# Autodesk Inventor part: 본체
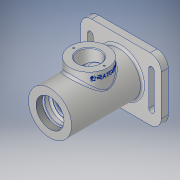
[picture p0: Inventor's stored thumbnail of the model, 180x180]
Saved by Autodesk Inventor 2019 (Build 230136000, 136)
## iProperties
Created: 2021-07
Part Number: 본체
Material: 알루미늄 6061
Document SubType Name: Modeling
Designer: jun-2-10
Mass: 738.051 g
Surface Area: 647.155 cm^2
Volume: 273.352 cm^3
Density: 2.7 g/cm^3
Appearance: 알루미늄 - 평지
Author: jun-2-10
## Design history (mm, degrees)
sketch "스케치1"
  geometry: C1 r 31 at (0, 0); 1 further point
  constraints: 1 centre point, 1 coincident
  dimensions: "d0" = 62 diameter of C1
extrude "돌출1" new body sketch "스케치1" stored distance "d1" = 115; taper "d2" = 0 deg
sketch "스케치2"
  geometry: C1 r 35 at (0, 0); 1 further point
  constraints: 1 centre point, 1 coincident
  dimensions: "d3" = 70 diameter of C1
extrude "돌출2" join sketch "스케치2" distance "d4" = 3; taper "d5" = 0 deg
sketch "스케치3"
  geometry: L1 (-58, 45)-(58, 45); L2 (58, 45)-(58, -45); L3 (58, -45)-(-58, -45); L4 (-58, -45)-(-58, 45); L5 (-58, 45)-(58, -45); L6 (58, 45)-(-58, -45); 1 further point
  constraints: 12 end point, 2 midpoint, 2 parallel, 1 horizontal, 1 perpendicular
  dimensions: "d6" = 116 distance of L1.start L1.end; "d7" = 90 distance of L1.end L2.end
extrude "돌출3" join sketch "스케치3" distance "d8" = 10; taper "d9" = 0 deg
sketch "스케치4"
  geometry: L1 (17.5, 31.5)-(17.5, 20.5); L2 (17.5, 20.5)-(23, 20.5); L3 (26, 17.5)-(26, -14.5); L4 (23, -17.5)-(17.5, -17.5); L5 (17.5, -17.5)-(17.5, -28.5); L6 (17.5, -28.5)-(16, -28.5); L7 (16, -28.5)-(16, -30.5); L8 (13, -33.5)-(10, -33.5); L9 (10, -33.5)-(10, -36.2); L10 (16.779, -45.318)-(22, -57.5); L11 (0, 80.5)-(0, -80.5) reference; L12 (31, -44.5)-(31, 57.5) reference; L13 (-31, -44.5)-(-31, 57.5) reference; L14 (35, -57.5)-(-35, -57.5) reference; L15 (14.022, -43.5)-(12.5, -43.5); L16 (12.5, -43.5)-(12.5, -36.5); L17 (12.2, -36.2)-(10, -36.2); L18 (17.5, 31.5)-(18.5, 31.5); L19 (18.5, 31.5)-(18.5, 33.25); L20 (18.5, 33.25)-(17.5, 33.25); L21 (17.5, 33.25)-(17.5, 36.5); L22 (17.5, 36.5)-(17, 36.5); L23 (20, 39.5)-(20, 45.5); L24 (20, 45.5)-(24, 45.5); L25 (24, 45.5)-(24, 48.5); L26 (24, 48.5)-(21, 48.5); L27 (31, 57.5)-(-31, 57.5) reference; L28 (22, -57.5)-(0, -57.5); L29 (21, 48.5)-(0, 48.5); L30 (0, 48.5)-(0, -57.5); A1 r 3 centre (17, 39.5) between (17, 36.5) and (20, 39.5); A2 r 3 centre (13, -30.5) between (13, -33.5) and (16, -30.5); A3 r 0.3 centre (12.2, -36.5) between (12.5, -36.5) and (12.2, -36.2); A4 r 3 centre (23, 17.5) between (26, 17.5) and (23, 20.5); A5 r 3 centre (23, -14.5) between (23, -17.5) and (26, -14.5); A6 r 3 centre (14.022, -46.5) between (16.779, -45.318) and (14.022, -43.5); 7 further points
  constraints: 50 end point, 20 perpendicular, 12 point on circle, 12 tangent, 10 point on line, 6 centre point, 2 horizontal, 1 equal radius, 1 midpoint
  dimensions: "d11" = 14 vertical distance of L10.end point (16, -43.5); "d12" = 44 diameter of L10.end L11; "d13" = 32 diameter of point (16, -43.5) L11; "d14" = 24 distance between parallel lines of L14 L8; "d15" = 20 diameter of L9 L11; "d16" = 52 diameter of L3 L11; "d17" = 35 diameter of L1 L11; "d18" = 11 distance of L4.end L5.end; "d20" = 7.3 distance of L15.end point (12.5, -36.2); "d21" = 25 diameter of L16 L11; "d22" = 32 diameter of L7 L11; "d23" = 35 diameter of L5 L11; "d24" = 38 distance of point (26, 20.5) point (26, -17.5); "d27" = 12 distance between parallel lines of L27 L24; "d29" = 1.75 distance of L18.end L19.end; "d30" = 37 diameter of L19 L11; "d31" = 35 diameter of L21 L11; "d32" = 21 distance between parallel lines of L27 L22; "d33" = 40 diameter of L23 L11; "d34" = 48 diameter of L25 L11; "d35" = 3 distance of L24.end L25.end; "d37" = 11 distance of L1.start L1.end; "d38" = 3 radius of A1; "d39" = 65 distance from line of L6 L21.end; "d40" = 3 radius of A2 (derived); "d41" = 0.3 radius of A3; "d42" = 3 radius of A4; "d43" = 3 radius of A6 (derived)
revolve "회전1" sketch "스케치4" stored, may be unused: angle "d44" = 90 deg
chamfer "모따기1" distance "d45" = 0.7; stored, may be unused: second distance "d46" = 2, angle "d47" = 30 deg
sketch "스케치7"
  geometry: 2 further points
  constraints: 1 coincident
hole "구멍1" sketch "스케치7" at (0, 0) diameter "d48" = 40.376; stored, may be unused: countersink angle "d52" = 90 deg, drill point angle "d54" = 0 deg; dims "d49" = 9, "d50" = 4, "d51" = 2, "d53" = 9
fillet "모깎기1" dims "d55" = 16
node "작업 평면1"
sketch "스케치9"
  geometry: L1 (0, -80.5)-(0, 80.5) reference; L2 (-81.2, 0)-(81.2, 0) reference; L3 (31, 57.5)-(-31, 57.5) reference; C1 r 27 at (0, 1.5); 1 further point
  constraints: 1 centre point, 1 point on line
  dimensions: "d58" = 54 diameter of C1; "d59" = 56 distance from line of L3 C1.centre
extrude "돌출4" join sketch "스케치9" stored distance "d60" = 10; taper "d61" = 0 deg
sketch "스케치10"
  geometry: C1 r 27 at (0, 0) reference; C2 r 16 at (0, 0); 1 further point
  constraints: 1 centre point, 1 coincident
  dimensions: "d62" = 32 diameter of C2
extrude "돌출5" cut sketch "스케치10" stored distance "d63" = 10; taper "d64" = 0 deg
sketch "스케치11"
  geometry: L1 (0, 82)-(0, -79) reference; L2 (22, 0)-(-22, 0); L3 (-31, -56)-(31, -56) reference; C1 r 16 at (0, 0) reference; C2 r 27 at (0, 0) reference; A1 r 22 centre (0, 0) between (22, 0) and (-22, 0); 3 further points
  constraints: 3 coincident, 2 end point, 2 point on circle, 1 centre point, 1 horizontal
  dimensions: "d65" = 44 diameter of A1; "d66" = 56 distance between parallel lines of L3 L2
hole "구멍2" sketch "스케치11" at (-22, 0), (22, 0) diameter "d67" = 2.459; stored, may be unused: countersink angle "d71" = 90 deg, drill point angle "d73" = 118 deg; dims "d68" = 6, "d69" = 4, "d70" = 2, "d72" = 8
sketch "스케치12"
  geometry: L1 (-81.2, 0)-(81.2, 0) reference; L2 (0, -63)-(0, 63) reference; L3 (-44, -25)-(-44, 25); L4 (-48, -25)-(-48, 25); L5 (-40, 25)-(-40, -25); L6 (44, -25)-(44, 25); L7 (40, -25)-(40, 25); L8 (48, 25)-(48, -25); A1 r 4 centre (-44, -25) between (-48, -25) and (-40, -25); A2 r 4 centre (-44, 25) between (-40, 25) and (-48, 25); A3 r 4 centre (44, -25) between (40, -25) and (48, -25); A4 r 4 centre (44, 25) between (48, 25) and (40, 25); 3 further points
  constraints: 16 end point, 8 point on circle, 8 tangent, 4 centre point, 2 midpoint, 2 parallel, 2 perpendicular, 2 point on line
  dimensions: "d74" = 4 radius of A4; "d75" = 50 distance of L6.start L6.end; "d76" = 50 distance of L3.start L3.end; "d77" = 44 distance between parallel lines of L6 L2; "d78" = 44 distance between parallel lines of L2 L3; "d79" = 4 radius of A2
extrude "돌출6" cut sketch "스케치12" extent not by distance; stored distance "d80" = 10; taper "d81" = 0 deg
fillet "모깎기2" dims "d82" = 3
chamfer "모따기2" distance "d83" = 1; stored, may be unused: second distance "d84" = 2, angle "d85" = 30 deg
node "작업 평면2"
sketch "스케치14"
  geometry: L1 (42, -15.5)-(42, 18.5) reference; L2 (42, 1.5)-(-31, 1.5); L3 (-31, -41.5)-(-31, 57.5) reference; 2 further points
  constraints: 2 end point, 2 point on line, 1 horizontal, 1 midpoint, 1 other
  dimensions: "d87" = 8 distance from line of L1 point (34, 1.5)
feature "엠보싱1" sketch "스케치14" dims "d88" = 0.5, "d89" = 0
chamfer "모따기3" distance "d90" = 1; stored, may be unused: second distance "d91" = 2, angle "d92" = 30 deg
fillet "모깎기3" dims "d93" = 0.3
chamfer "모따기4" distance "d94" = 0.7; stored, may be unused: second distance "d95" = 2, angle "d96" = 30 deg
node "솔리드1"
node "투영된 루프1"
node "투영된 루프2"
other parameters: "d56" = 42, "d86" = 67
